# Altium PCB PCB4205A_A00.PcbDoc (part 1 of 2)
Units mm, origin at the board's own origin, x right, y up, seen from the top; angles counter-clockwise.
Board outline 30 x 60 mm, 4 copper layers (Top Layer, Signal Layer 2, Signal Layer 3, Bottom Layer), stack 1.526 mm thick; 55 components, 66 nets, 233 pads, 356 vias.
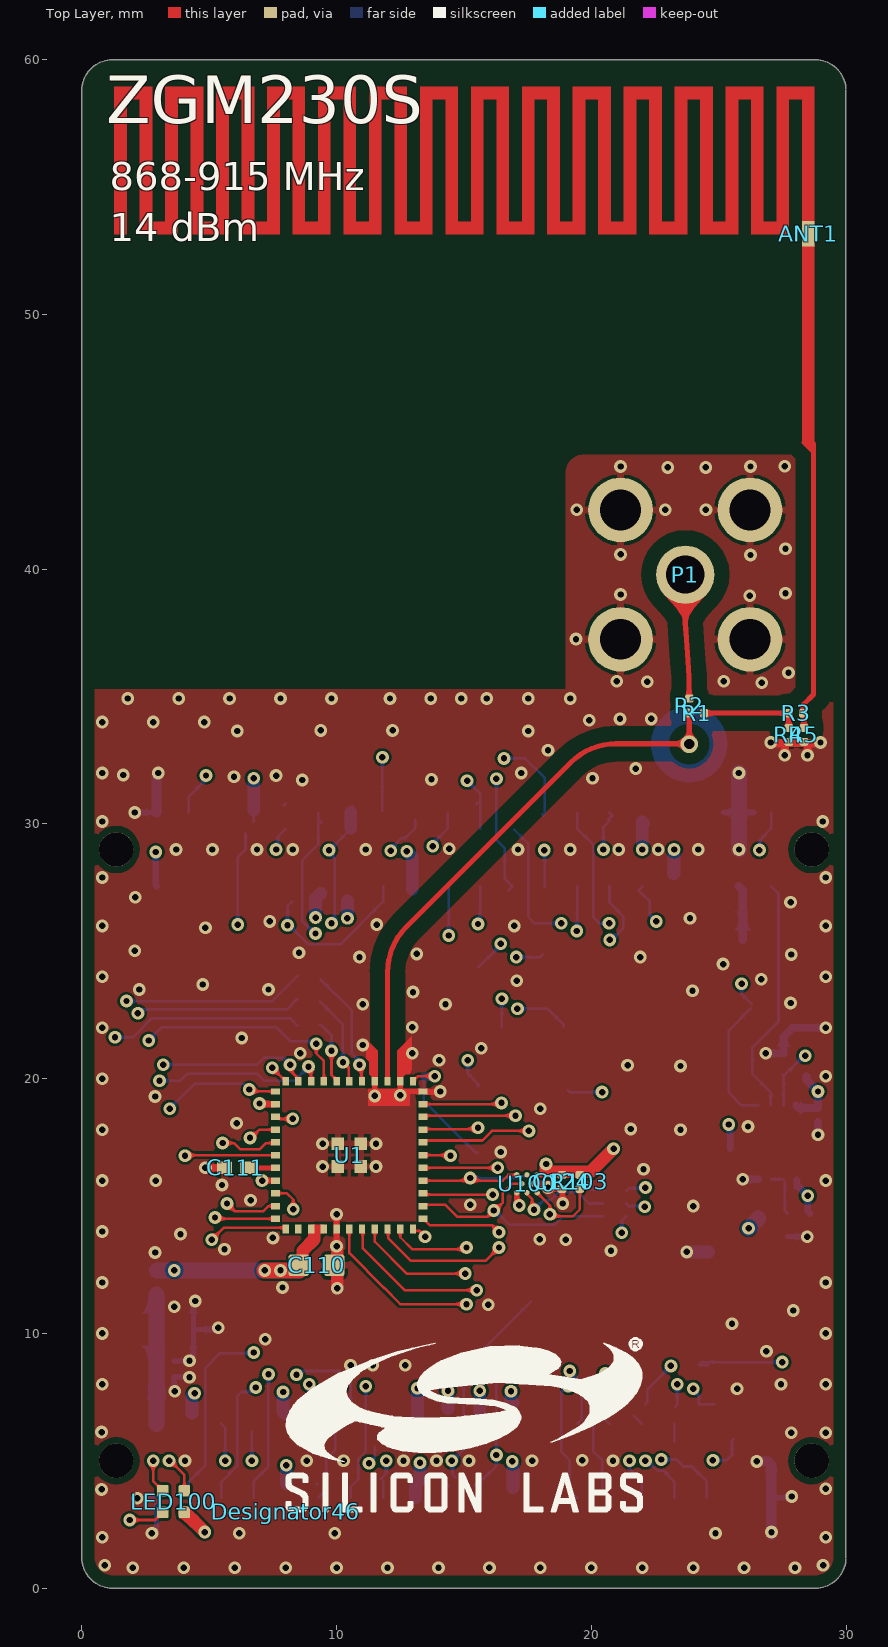
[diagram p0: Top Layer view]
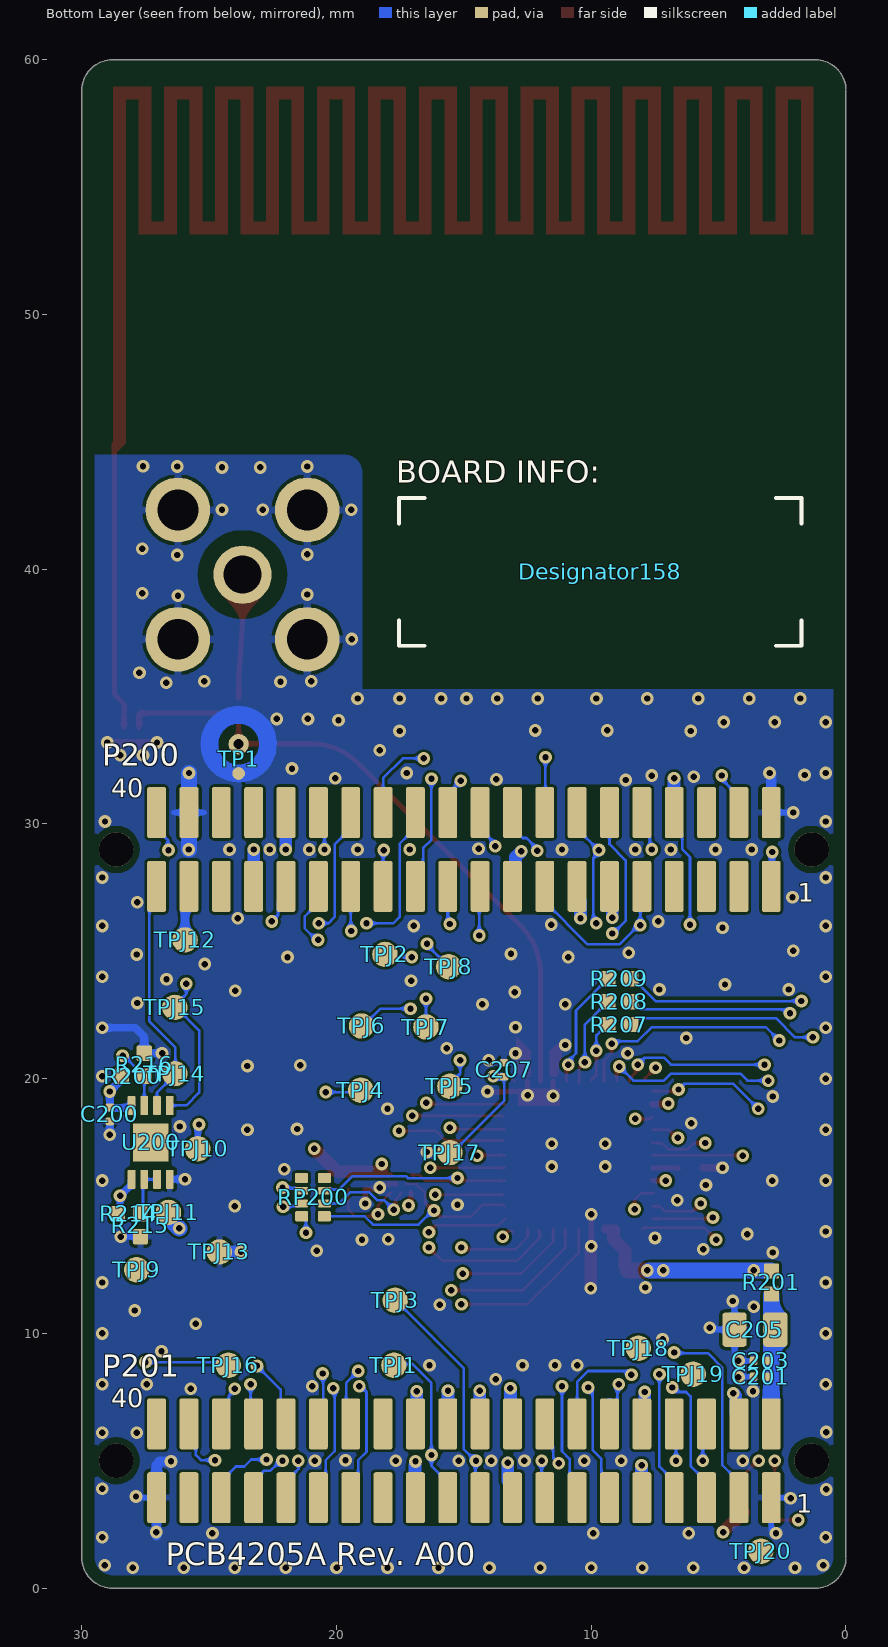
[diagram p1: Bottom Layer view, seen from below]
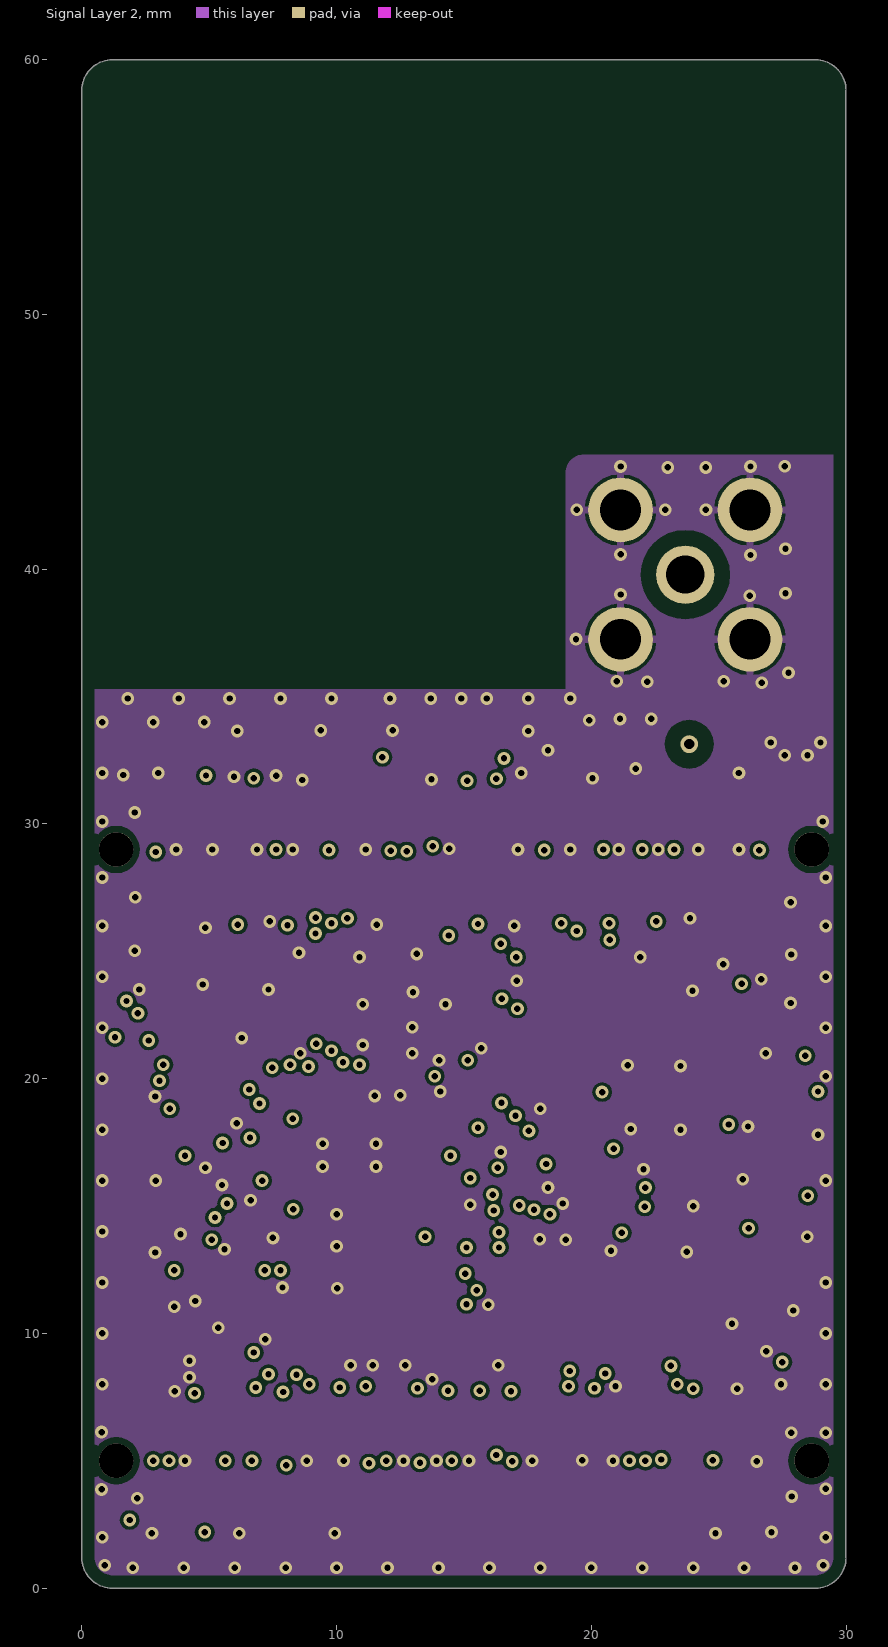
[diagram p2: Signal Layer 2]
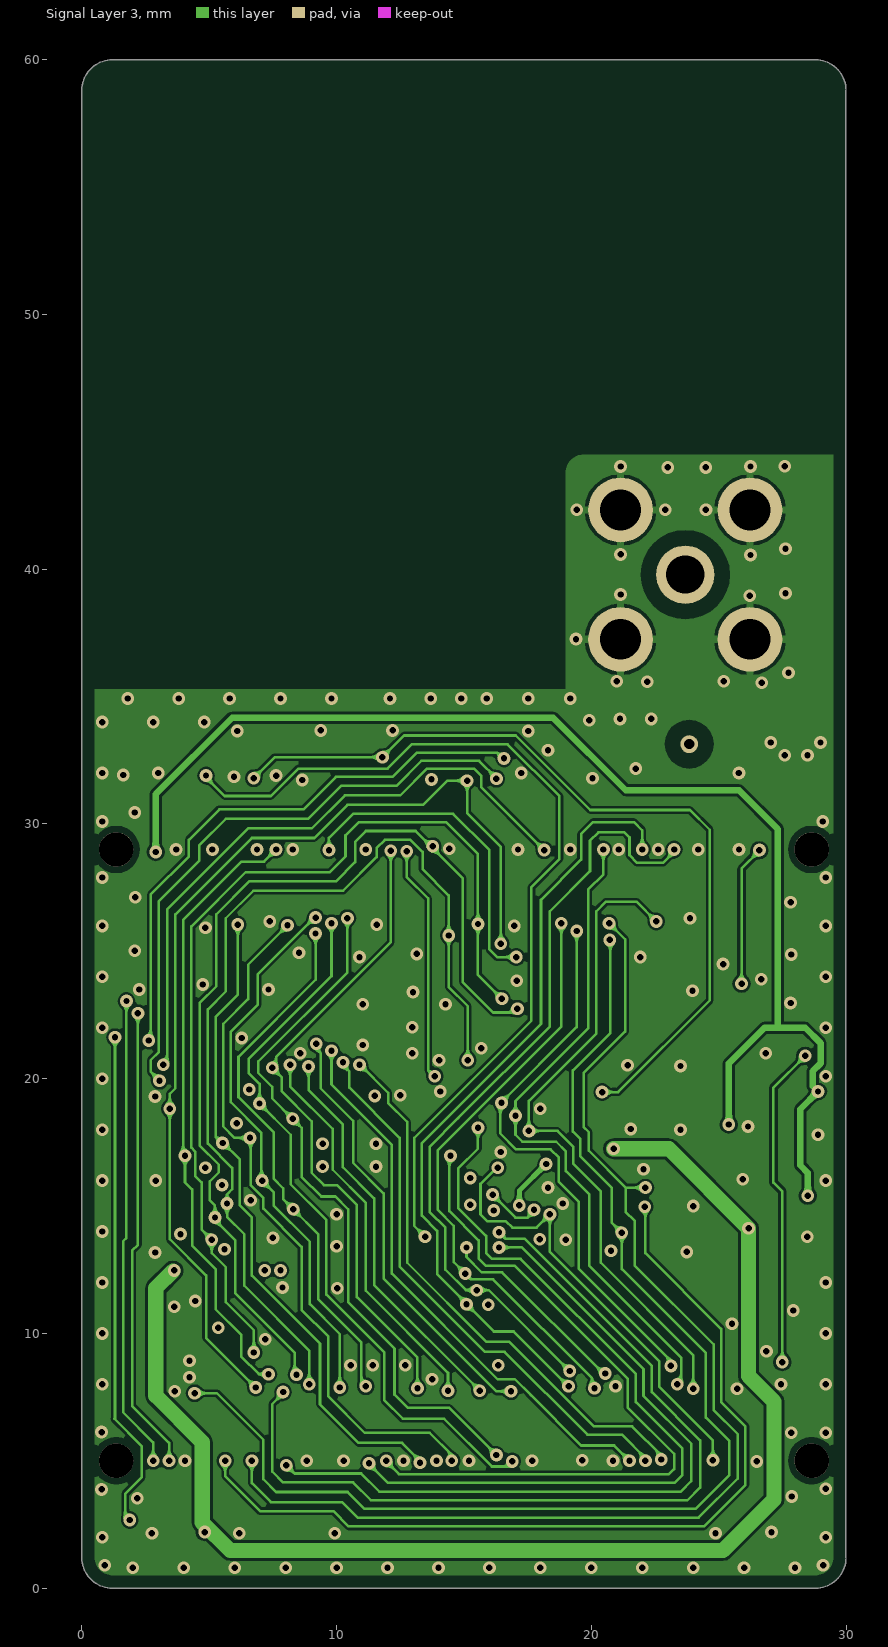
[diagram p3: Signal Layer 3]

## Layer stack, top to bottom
Top Solder: solder mask 0.01, Solder Resist, Dk 3.5
Top Layer: signal copper 0.035
Dielectric 1: core 0.132, 2116, Dk 4.2
Signal Layer 2: signal copper 0.018
Dielectric 3: prepreg 1.156, Dk 4.2
Signal Layer 3: signal copper 0.018
Dielectric 2: core 0.132, 2116, Dk 4.2
Bottom Layer: signal copper 0.035
Bottom Solder: solder mask 0.01, Solder Resist, Dk 3.5

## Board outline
0,1.2 ccw(c1.2,1.2) 1.2,0 28.8,0 ccw(c28.8,1.2) 30,1.2 30,58.8 ccw(c28.8,58.8) 28.8,60 1.2,60 ccw(c1.2,58.8) 0,58.8

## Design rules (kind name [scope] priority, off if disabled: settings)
AcuteAngle [All] p1: minimum=6.00000000000000E+0001 checktracksonly=FALSE
BoardOutlineClearance [All] p1: gap=0.5
Clearance Clearance_to_Holes [(InPadClass('NPTH')) and (HoleDiameter > AsMM(0.01))] p1: gap=0.254
Clearance Clearance_50Ohm [InNetClass('50Ohm') or InNet('50R_*') vs InPolygon] p2: gap=0.6
Clearance Clerance_Polygon_GND3 [InNamedPolygon('GND_3')] p3: gap=0.127
Clearance Clerance_Polygon_GND2 [InNamedPolygon('GND_2')] p4: gap=0.127
Clearance Clerance_Polygon_GND1 [InNamedPolygon('GND_L2')] p5: gap=0.127
Clearance Clerance_Polygon_GND4 [InNamedPolygon('GND_4')] p6: gap=0.127
Clearance Clearance_General [All] p7: gap=0.1
ComponentClearance Res_selector [InComponent('R1') or InComponent('R203')    or InComponent('R205') or InComponent('R214') or InComponent('R216') vs InComponent('R2') or InComponent('R204') or InComponent('R206')  or InComponent('R215') or InComponent('R200')] p1: gap=0 collisioncheckmode=3 verticalgap=0 showdistances=FALSE
ComponentClearance ComponentClearance_R1_R2 [InComponent('R1') vs InComponent('R2')] p2: gap=0 collisioncheckmode=3 verticalgap=0 showdistances=TRUE
ComponentClearance [All] p3: gap=0.2 collisioncheckmode=3 verticalgap=0.2 showdistances=TRUE
HoleToHoleClearance HoleToHoleClearance_ANT1toPAD [Incomponent ('ANT1') vs ISpad] p1: gap=0 allowstackedmicrovias=TRUE
HoleToHoleClearance HoleToHoleClearance_U1toVIA_1 [InComponent ('U1') vs IsVia] p2: gap=0 allowstackedmicrovias=TRUE
HoleToHoleClearance [All] p3: gap=0.254 allowstackedmicrovias=TRUE
MinimumSolderMaskSliver [All] p1: minsoldermaskwidth=0.102
NetAntennae [not InComponent('ANT1')] p1: netantennaetolerance=0
PolygonConnect PolygonConnect_SH100 [InComponent('SH100')] p1: connectstyle=Direct reliefconductorwidth=0.254 reliefentries=4 polygonreliefangle="90 Angle" airgapwidth=0.127
PolygonConnect PolygonConnect_P1 [InComponent('P1')] p2: connectstyle=Relief reliefconductorwidth=0.305 reliefentries=4 polygonreliefangle="90 Angle" airgapwidth=0.127
PolygonConnect Polygon_VIA_Connect [IsVia] p3: connectstyle=Direct reliefconductorwidth=0.254 reliefentries=4 polygonreliefangle="90 Angle" airgapwidth=0.254
PolygonConnect PolygonConnect_General [All] p4: connectstyle=Relief reliefconductorwidth=0.254 reliefentries=4 polygonreliefangle="90 Angle" airgapwidth=0.127
RoutingVias [All] p1: holewidth=0.25 width=0.5 viastyle="Through Hole" minholewidth=0.25 minwidth=0.5 maxholewidth=1 maxwidth=1.5
SilkToSilkClearance [All] p1: silktosilkclearance=0.102
SilkToSolderMaskClearance [IsPad] p1: minsilkscreentomaskgap=0.102 clearancetoexposedcopper=TRUE
SolderMaskExpansion [All] p1: expansion=0.051
ViasUnderSMD [(PadXSize_TopLayer > AsMM(1)) and (PadySize_TopLayer > AsMM(1))] p1: allowed=TRUE
Width [All] p1: maxlimit=5.08 minlimit=0.1 preferedwidth=0.127
24 further rules are at their usual default settings.

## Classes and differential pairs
net class 50Ohm: 50R_P1 50R_R1 50R_R4 N16865893
pad class NPTH: P200-M1 P200-M2 P201-M1 P201-M2

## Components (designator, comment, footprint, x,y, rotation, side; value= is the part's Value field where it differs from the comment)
ANT1 "Antenna" SWL_ANTENNA 1.27,53.15 r0 top
C110 "10U" C0603_L 9.213,12.672 r0 top
C111 "TBD" C0402_L 6.05,16.5 r180 top
C124 "100N" C0201_L 18.85,15.95 r270 top
C200 "100N" C0201_L 28.9,18.6 r270 bottom
C201 "100N" C0201_L 3.35,8.3 r0 bottom
C203 "100N" C0201_L 3.35,8.925 r0 bottom
C205 "10U" C0805_L 3.575,10.15 r0 bottom
C207 "100N" C0201_L 13.425,20.35 r90 bottom
Designator43 "Comment" PCB_SPEC_4_LAYER_ZWAVE -73.325,112.975 r0 top locked
Designator46 "Comment" LOGO_SILABS_W14.0 8,3 r0 top
Designator158 "Comment" PCB_Info_16x6 9.65,39.9 r180 bottom
LED100 "RGB" LED_LUMEX_SML_LX0404 3.6,3.4 r90 top
P1 "SMA" TE_SMA_TH_1814832 23.69,39.79 r0 top
P200 "SOCKET_WCON_2X20_1.27MM_SMD" SAM_SFC-120-T2-D-A-2X20_SNUM 15,29 r0 bottom locked
P201 "SOCKET_WCON_2X20_1.27MM_SMD" SAM_SFC-120-T2-D-A-2X20_SNUM 15,5 r0 bottom locked
R1 "0R" R0201_L 24.15,34.35 r0 top
R2 "0R" R0201_L 23.85,34.65 r90 top
R3 "0R" R0201_L 28.04,34.35 r0 top
R4 "0R" R0201_L 27.75,33.5 r270 top
R5 "0R" R0201_L 28.35,33.5 r270 top
R103 "330K" R0201_L 19.55,15.95 r90 top
R200 "10K" R0402_L 28,20.1 r0 bottom
R201 "0R" R0402_L 2.925,12 r90 bottom
R207 "8K2" R0402_L 8.9,22.125 r180 bottom
R208 "5K6" R0402_L 8.9,23.025 r180 bottom
R209 "4K7" R0402_L 8.9,23.925 r180 bottom
R214 "0R" R0402_L 28.15,14.7 r180 bottom
R215 "0R" R0402_L 27.7,14.25 r270 bottom
R216 "0R" R0402_L 27.55,20.55 r90 bottom
RP200 "100R" RES_MNR04-8 20.925,15.35 r90 bottom
TP1 "TP_RF" "TP_INGUN_50_OHM_CLOSED openvia" 23.845,33.135 r180 bottom
TPJ1 "TPJ_SMD" TP_1.0_SMD 17.75,8.75 r90 bottom locked
TPJ2 "TPJ_SMD" TP_1.0_SMD 18.1,24.88 r90 bottom locked
TPJ3 "TPJ_SMD" TP_1.0_SMD 17.7,11.3 r90 bottom locked
TPJ4 "TPJ_SMD" TP_1.0_SMD 19.05,19.55 r90 bottom locked
TPJ5 "TPJ_SMD" TP_1.0_SMD 15.55,19.7 r90 bottom locked
TPJ6 "TPJ_SMD" TP_1.0_SMD 19.02,22.07 r90 bottom locked
TPJ7 "TPJ_SMD" TP_1.0_SMD 16.49,22.03 r90 bottom locked
TPJ8 "TPJ_SMD" TP_1.0_SMD 15.6,24.4 r90 bottom locked
TPJ9 "TPJ_SMD" TP_1.0_SMD 27.85,12.5 r90 bottom locked
TPJ10 "TPJ_SMD" TP_1.0_SMD 25.45,17.25 r90 bottom locked
TPJ11 "TPJ_SMD" TP_1.0_SMD 26.6,14.75 r90 bottom locked
TPJ12 "TPJ_SMD" TP_1.0_SMD 25.95,25.45 r90 bottom locked
TPJ13 "TPJ_SMD" TP_1.0_SMD 24.6,13.2 r90 bottom locked
TPJ14 "TPJ_SMD" TP_1.0_SMD 26.35,20.2 r90 bottom locked
TPJ15 "TPJ_SMD" TP_1.0_SMD 26.35,22.8 r90 bottom locked
TPJ16 "TPJ_SMD" TP_1.0_SMD 24.25,8.75 r90 bottom locked
TPJ17 "TPJ_SMD" TP_1.0_SMD 15.55,17.1 r90 bottom locked
TPJ18 "TPJ_SMD" TP_1.0_SMD 8.15,9.42 r90 bottom locked
TPJ19 "TPJ_SMD" TP_1.0_SMD 6,8.4 r90 bottom locked
TPJ20 "TPJ_SMD" TP_1.0_SMD 3.34,1.45 r90 bottom locked
U1 "ZGM230SA27HNN0" ZGM230S 10.5,17 r270 top locked
U100 "MX25R8035F" BGA8_M040_1.24x1.75_WLCSP 17.475,15.875 r270 top
U200 "24AA024" TDFN8_M050_2.0X3.0_EP 27.3,17.5 r180 bottom

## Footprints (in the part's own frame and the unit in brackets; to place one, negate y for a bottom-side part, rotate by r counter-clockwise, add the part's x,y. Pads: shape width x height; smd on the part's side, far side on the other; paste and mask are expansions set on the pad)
BGA8_M040_1.24x1.75_WLCSP [mm] "BGA, 8 pin. U100"
  round 0.21 smd mask+0.051: A1(-0.35,0.4) A3(0.35,0.4) B2(0,0.2) C1(-0.35,0) C3(0.35,0) D2(0,-0.2) E1(-0.35,-0.4) E3(0.35,-0.4)
  body extent -0.63,-0.89 0.63,0.88, height 0.52
C0201_L [mm] "Capacitor, Chip; 0.60 mm L X 0.30 mm W X 0.33 mm H body"
  rrect52% 0.31x0.34 smd: 1(-0.275,0) 2(0.275,0)
  body extent -0.3,-0.15 0.3,0.15, height 0.3
C0402_L [mm] "Chip Capacitor, 2-Leads, Body 1.0x0.5mm, IPC High Density"
  rrect20% 0.6x0.5 smd mask+0.051: 1(-0.45,0) 2(0.45,0)
  body extent -0.5,-0.25 0.5,0.25, height 0.6
C0603_L [mm] "Capacitor, 0603, High Density (C)"
  rrect25% 0.8x0.85 smd: 1(-0.7,0) 2(0.7,0)
  body extent -0.88,-0.48 0.87,0.48, height 0.95
C0805_L [mm] "Capacitor, 0805"
  rrect25% 0.95x1.35 smd: 1(-0.8,0) 2(0.8,0)
  body extent -1.1,-0.72 1.1,0.72, height 1.45
LED_LUMEX_SML_LX0404 [mm] "LED, LUMEX, SML LX0404 1.0x1.0x0.25 NB! Pin numbering"
  rrect25% 0.45x0.45 smd mask+0.05: 1(-0.425,-0.425) 2(-0.425,0.425) 3(0.425,0.425) 4(0.425,-0.425)
  body extent -0.5,-0.5 0.5,0.5, height 0.31
LOGO_SILABS_W14.0 [mm] "LOGO_SILABS_W14.0"
  silkscreen extent 0.03,0 13.99,6.83
PCB_Info_16x6 [mm]
  silkscreen extent -7.9,-2.9 7.9,2.9
PCB_SPEC_4_LAYER_ZWAVE [mm]
R0201_L [mm] "Resistor, Chip; 0.60 mm L X 0.30 mm W X 0.28 mm H body"
  rrect52% 0.31x0.34 smd: 1(-0.275,0) 2(0.275,0)
  body extent -0.3,-0.15 0.3,0.15, height 0.23
R0402_L [mm] "Chip Resistor, 2-Leads, Body 1.0x0.5mm, IPC High Density"
  rrect20% 0.6x0.6 smd mask+0.051: 1(-0.45,0) 2(0.45,0)
  body extent -0.5,-0.25 0.5,0.25, height 0.6
RES_MNR04-8 [mm] "Chip resistor network 8pin"
  rrect20% 0.4x0.5 smd mask+0.051: 1(-0.75,-0.45) 4(0.75,-0.45) 5(0.75,0.45) 8(-0.75,0.45)
  rrect20% 0.3x0.5 smd mask+0.051: 2(-0.25,-0.45) 3(0.25,-0.45) 6(0.25,0.45) 7(-0.25,0.45)
  body extent -1,-0.4 1,0.4, height 0.5
SAM_SFC-120-T2-D-A-2X20_SNUM [mm]
  rrect20% 0.74x2 smd mask+0.05: 1(-12.065,1.45) 2(-12.065,-1.45) 3(-10.795,1.45) 4(-10.795,-1.45) 5(-9.525,1.45) 6(-9.525,-1.45) 7(-8.255,1.45) 8(-8.255,-1.45) 9(-6.985,1.45) 10(-6.985,-1.45) 11(-5.715,1.45) 12(-5.715,-1.45) 13(-4.445,1.45) 14(-4.445,-1.45) 15(-3.175,1.45) 16(-3.175,-1.45) 17(-1.905,1.45) 18(-1.905,-1.45) 19(-0.635,1.45) 20(-0.635,-1.45) 21(0.635,1.45) 22(0.635,-1.45) 23(1.905,1.45) 24(1.905,-1.45) 25(3.175,1.45) 26(3.175,-1.45) 27(4.445,1.45) 28(4.445,-1.45) 29(5.715,1.45) 30(5.715,-1.45) 31(6.985,1.45) 32(6.985,-1.45) 33(8.255,1.45) 34(8.255,-1.45) 35(9.525,1.45) 36(9.525,-1.45) 37(10.795,1.45) 38(10.795,-1.45) 39(12.065,1.45) 40(12.065,-1.45)
  round 1.35 hole 1.35 unplated paste-5.563 mask-5.563: M1(13.652,0) M2(-13.652,0)
  body extent -14.29,-2.1 14.29,2.16, height 4.67
SWL_ANTENNA [mm] "switchless antenna"
  rect 0.5x1 smd paste-1 mask-1: 1(27.25,0.02)
  Top Layer region: 0,5.3 1.5,5.3 1.5,5.8 0,5.8
  Top Layer region: 2,5.3 3.5,5.3 3.5,5.8 2,5.8
  Top Layer region: 4,5.3 5.5,5.3 5.5,5.8 4,5.8
  Top Layer region: 6,5.3 7.5,5.3 7.5,5.8 6,5.8
  Top Layer region: 8,5.3 9.5,5.3 9.5,5.8 8,5.8
  Top Layer region: 10,5.3 11.5,5.3 11.5,5.8 10,5.8
  Top Layer region: 12,5.3 13.5,5.3 13.5,5.8 12,5.8
  Top Layer region: 14,5.3 15.5,5.3 15.5,5.8 14,5.8
  Top Layer region: 16,5.3 17.5,5.3 17.5,5.8 16,5.8
  Top Layer region: 18,5.3 19.5,5.3 19.5,5.8 18,5.8
  Top Layer region: 20,5.3 21.5,5.3 21.5,5.8 20,5.8
  Top Layer region: 22,5.3 23.5,5.3 23.5,5.8 22,5.8
  Top Layer region: 24,5.3 25.5,5.3 25.5,5.8 24,5.8
  Top Layer region: 26,5.3 27.5,5.3 27.5,5.8 26,5.8
  Top Layer region: 25,0 26.5,0 26.5,0.5 25,0.5
  Top Layer region: 23,0 24.5,0 24.5,0.5 23,0.5
  Top Layer region: 21,0 22.5,0 22.5,0.5 21,0.5
  Top Layer region: 19,0 20.5,0 20.5,0.5 19,0.5
  Top Layer region: 17,0 18.5,0 18.5,0.5 17,0.5
  Top Layer region: 15,0 16.5,0 16.5,0.5 15,0.5
  Top Layer region: 13,0 14.5,0 14.5,0.5 13,0.5
  Top Layer region: 11,0 12.5,0 12.5,0.5 11,0.5
  Top Layer region: 9,0 10.5,0 10.5,0.5 9,0.5
  Top Layer region: 7,0 8.5,0 8.5,0.5 7,0.5
  Top Layer region: 5,0 6.5,0 6.5,0.5 5,0.5
  Top Layer region: 3,0 4.5,0 4.5,0.5 3,0.5
  Top Layer region: 1,0 2.5,0 2.5,0.5 1,0.5
  Top Layer region: 24,0 24.5,0 24.5,5.8 24,5.8
  Top Layer region: 25,0 25.5,0 25.5,5.8 25,5.8
  Top Layer region: 26,0 26.5,0 26.5,5.8 26,5.8
  Top Layer region: 27,-0.5 27.5,-0.5 27.5,5.8 27,5.8
  Top Layer region: 18,0 18.5,0 18.5,5.8 18,5.8
  Top Layer region: 19,0 19.5,0 19.5,5.8 19,5.8
  Top Layer region: 20,0 20.5,0 20.5,5.8 20,5.8
  Top Layer region: 21,0 21.5,0 21.5,5.8 21,5.8
  Top Layer region: 22,0 22.5,0 22.5,5.8 22,5.8
  Top Layer region: 23,0 23.5,0 23.5,5.8 23,5.8
  Top Layer region: 12,0 12.5,0 12.5,5.8 12,5.8
  Top Layer region: 13,0 13.5,0 13.5,5.8 13,5.8
  Top Layer region: 14,0 14.5,0 14.5,5.8 14,5.8
  Top Layer region: 15,0 15.5,0 15.5,5.8 15,5.8
  Top Layer region: 16,0 16.5,0 16.5,5.8 16,5.8
  Top Layer region: 17,0 17.5,0 17.5,5.8 17,5.8
  Top Layer region: 6,0 6.5,0 6.5,5.8 6,5.8
  Top Layer region: 7,0 7.5,0 7.5,5.8 7,5.8
  Top Layer region: 8,0 8.5,0 8.5,5.8 8,5.8
  Top Layer region: 9,0 9.5,0 9.5,5.8 9,5.8
  Top Layer region: 10,0 10.5,0 10.5,5.8 10,5.8
  Top Layer region: 11,0 11.5,0 11.5,5.8 11,5.8
  Top Layer region: 5,0 5.5,0 5.5,5.8 5,5.8
  Top Layer region: 4,0 4.5,0 4.5,5.8 4,5.8
  Top Layer region: 3,0 3.5,0 3.5,5.8 3,5.8
  Top Layer region: 2,0 2.5,0 2.5,5.8 2,5.8
  Top Layer region: 1,0 1.5,0 1.5,5.8 1,5.8
  Top Layer region: 0,0 0.5,0 0.5,5.8 0,5.8
TDFN8_M050_2.0X3.0_EP [mm] "TDFN8_M050_2.0x3.0_EP"
  rrect20% 0.3x0.75 smd mask+0.051: 1(-0.75,-1.45) 2(-0.25,-1.45) 3(0.25,-1.45) 4(0.75,-1.45) 5(0.75,1.45) 6(0.25,1.45) 7(-0.25,1.45) 8(-0.75,1.45)
  rect 1.4x1.5 smd mask+0.051: 9(0,0)
  body extent -1,-1.5 1,1.5, height 1
TE_SMA_TH_1814832 [mm]
  round 2.286 hole 1.5: 1(0,0)
  round 2.54 hole 1.6: 2(-2.54,-2.54) 3(2.54,-2.54) 4(2.54,2.54) 5(-2.54,2.54)
  body extent -3.2,-3.2 3.2,3.2, height 9.5
TP_1.0_SMD [mm] "Test Point, 1.0 mm, SMD"
  round 1 smd paste-0.501: 1(0,0)
  body extent -0.5,-0.5 0.5,0.5, height 0.01
"TP_INGUN_50_OHM_CLOSED openvia" [mm] "TP_INGUN_50_OHM_CLOSED"
  round 0.8 / inner round 0.7 / far side round 0.7 hole 0.4 mask+0: 1(0,0)
  round 0.5 smd paste-0.255 mask-0.41: 2(0,-1.15)
  Top Layer pour cut-out: 0,-0.8 0.4,-0.693 0.693,-0.4 0.8,0 0.693,0.4 0.4,0.693 0,0.8 0,0.8 -0.347,0.721 -0.625,0.499 -0.78,0.178 -0.78,-0.178 -0.625,-0.499 -0.347,-0.721 0,-0.8
  Top Layer lines w0.7: 0,-1.15 ccw(c0,0) -1.15,0 ccw(c0,0) 0,-1.15
ZGM230S [mm] "no datasheet"
  rect 0.35x0.25 smd paste-0.03 mask+0.04: 1(-2.9,2.5) 2(-2.9,2) 3(-2.9,1.5) 4(-2.9,1) 5(-2.9,0.5) 6(-2.9,0) 7(-2.9,-0.5) 8(-2.9,-1) 9(-2.9,-1.5) 10(-2.9,-2) 11(-2.9,-2.5) 23(2.9,-2.5) 24(2.9,-2) 25(2.9,-1.5) 26(2.9,-1) 27(2.9,-0.5) 28(2.9,0) 29(2.9,0.5) 30(2.9,1) 31(2.9,1.5) 32(2.9,2) 33(2.9,2.5)
  rect 0.25x0.35 smd paste-0.03 mask+0.04: 12(-2.5,-2.9) 13(-2,-2.9) 14(-1.5,-2.9) 15(-1,-2.9) 16(-0.5,-2.9) 17(0,-2.9) 18(0.5,-2.9) 19(1,-2.9) 20(1.5,-2.9) 21(2,-2.9) 22(2.5,-2.9) 34(2.5,2.9) 35(2,2.9) 36(1.5,2.9) 37(1,2.9) 38(0.5,2.9) 39(0,2.9) 40(-0.5,2.9) 41(-1,2.9) 42(-1.5,2.9) 43(-2,2.9) 44(-2.5,2.9)
  rect 0.5x0.5 smd paste-0.03 mask+0.04: 45(-0.45,0.45) 46(-0.45,-0.45) 47(0.45,-0.45) 48(0.45,0.45)
  body extent -3.25,-3.25 3.25,3.25, height 1.3

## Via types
v1: diameter 0.5, hole 0.25, Top Layer to Bottom Layer, tented both sides, 356 vias

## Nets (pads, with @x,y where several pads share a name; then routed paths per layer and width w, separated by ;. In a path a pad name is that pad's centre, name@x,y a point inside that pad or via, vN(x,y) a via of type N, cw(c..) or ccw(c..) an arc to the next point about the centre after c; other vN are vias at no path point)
3V3: C200.1 P200.1 R200.2 R214.1 TPJ10.1 U200.1 U200.8 | length 57.3
  Signal Layer 3 w0.254: v1(2.9,28.9) 2.9,31.175 5.9,34.175 18.5,34.175 21.35,31.325 25.8,31.325 27.325,29.8 27.325,22.05 ; v1(25.4,18.2) 25.4,20.6 26.8,22 28.4,22 29,21.4 29,20.6 28.7,20.3 28.7,19.7 v1(28.9,19.5) 28.2,18.8 28.2,16.6 28.5,16.3 v1(28.5,15.4)
  Bottom Layer w0.254: v1(2.9,28.9) 2.9,27.585 P200.1@2.935,27.55 ; v1(25.4,18.2) 25.45,18.25 TPJ10.1@25.45,17.25 ; U200.1@28.075,16.025 28.075,15.825 v1(28.5,15.4) 28.5,14.8 R214.1@28.6,14.7
  Bottom Layer w0.305: U200.8@28.05,18.95 28.15,18.85 28.9,18.85 C200.1@28.9,18.875 v1(28.9,19.5) 28.45,19.95 R200.2@28.45,20.1
5V: P200.37 TPJ12.1 | length 2.2
  Bottom Layer w0.33: P200.37@25.795,27.55 25.95,27.395 TPJ12.1@25.95,25.45
50R_P1: P1.1 R2.2 | length 4.8
  Top Layer w0.2: P1.1@23.69,39.79 23.69,37.9 23.734,37.25 23.791,36.399 23.84,35.775 23.84,34.96 R2.2@23.85,34.95
50R_R1: R1.1 R2.1 TP1.1 U1.3 | length 21.4
  Top Layer w0.2: U1.3@12,19.9 12,24.173 cw(c14.54,24.173) 12.744,25.969 19.181,32.406 cw(c20.977,30.61) 20.977,33.15 TP1.1@23.845,33.15 ; R1.1@23.84,34.35 23.845,34.345 TP1.1@23.845,33.15 ; TP1.1@23.85,33.15 TP1.1@23.845,33.15
50R_R4: R1.2 R3.1 R4.1 | length 3.8
  Top Layer w0.2: R1.2@24.45,34.35 27.74,34.35 27.75,34.34 R4.1@27.75,33.8
BOARD_ID_SCL: P200.39 TPJ14.1 U200.6 | length 9.3
  Bottom Layer w0.1: TPJ14.1@26.325,20.175 27.05,19.45 U200.6@27.05,18.95 ; TPJ14.1@26.325,20.275 26.325,21.225 27.35,22.25 27.35,27.265 P200.39@27.065,27.55
BOARD_ID_SDA: P200.40 TPJ15.1 U200.5 | length 13.1
  Signal Layer 3 w0.1: v1@25.9,23.75 25.9,28.25 26.6,28.95 v1(26.6,28.975)
  Bottom Layer w0.1: v1(25.9,23.725) 25.9,23.325 TPJ15.1@26.3,22.925 ; TPJ15.1@26.275,22.775 25.4,21.9 25.4,19.45 25.9,18.95 U200.5@26.55,18.95 ; v1@26.675,29.05 26.625,29.1 26.625,29.375 27.065,29.815 P200.40@27.065,30.45
BOARD_ID_WP: R200.1 R216.1 TPJ16.1 U200.7 | length 18.7
  Signal Layer 3 w0.1: v1(27.5,8.875) 27.5,15.575 27.15,15.925 27.15,19.65 v1(28.4,20.9)
  Bottom Layer w0.1: TPJ16.1@24.225,8.775 24.325,8.875 v1(27.5,8.875) ; TPJ16.1@24.25,8.75 TPJ16.1@24.595,8.75 ; R200.1@27.525,20.15 27.55,20.125 U200.7@27.55,18.95 ; R200.1@27.55,20.1 28.3,20.85 v1@28.375,20.85
FLASH_MISO: RP200.2 U1.36 U100.C3 | length 8.4
  Top Layer w0.1: U1.36@13.475,15.45 15.85,15.45 ; U100.C3@17.475,15.525 17.475,15.475 17.675,15.275 17.675,14.975 v1@17.725,14.925
  Signal Layer 3 w0.1: v1(16.125,15.45) 17.025,14.55 17.5,14.55 17.65,14.7 v1@17.65,14.9
  Bottom Layer w0.1: v1(17.751,14.851) 18.125,15.225 18.4,15.225 18.725,15.55 19.45,15.55 19.9,15.1 RP200.2@20.45,15.1
FLASH_MOSI: RP200.1 U1.35 U100.D2 | length 9.4
  Top Layer w0.1: U1.35@13.425,15 13.475,15.05 14.275,15.05 14.75,14.575 15.925,14.575 v1(16.175,14.825) ; v1@16.25,14.85 16.525,15.125 16.525,15.525 16.875,15.875 U100.D2@17.275,15.875
  Bottom Layer w0.1: v1(16.175,14.825) 16.2,14.85 16.775,14.275 18.575,14.275 18.9,14.6 RP200.1@20.475,14.6
FLASH_SCLK: RP200.3 U1.37 U100.E1 | length 9.3
  Top Layer w0.1: U1.37@13.4,16 16.525,16 16.75,16.225 U100.E1@17.075,16.225
  Bottom Layer w0.1: v1(15.25,16.1) 17.2,16.1 17.275,16.175 19.375,16.175 19.9,15.65 20.475,15.65 RP200.3@20.5,15.625
FLASH_SCS: P201.38 R103.1 U1.38 U100.A3 | length 25.2
  Top Layer w0.1: U1.38@13.4,16.5 16.125,16.5 16.25,16.625 16.325,16.55 v1(16.325,16.5) ; U100.A3@17.875,15.525 18.375,15.025 v1@18.375,14.7 ; v1@18.375,14.6 19.275,14.6 19.55,14.875 R103.1@19.55,15.675
  Signal Layer 3 w0.1: v1(16.325,16.5) 16.275,16.5 15.65,15.875 15.65,14.675 15.925,14.4 16.65,14.4 16.9,14.15 17.85,14.15 v1(18.375,14.675) 18.375,13.2 22.675,8.9 22.675,7.9 24.775,5.8 v1@24.775,5.05
  Bottom Layer w0.1: v1(24.775,5.025) 25.325,5.025 25.525,5.225 25.525,5.775 P201.38@25.6,5.85
GND: C110.2 C111.2 C124.2 C200.2 C201.2 C203.2 C205.2 C207.2 P1.2 P1.3 P1.4 P1.5 P200.2 P200.38 P201.1 P201.39 R4.2 R5.2 R215.2 R216.2 TP1.2 TPJ13.1 U1.2 U1.4 U1.27 U1.44 U1.45 U1.46 U1.47 U1.48 U100.B2 U200.4 | length 35.1
  Top Layer w0.2: v1@9.975,14.675 10,14.65 U1.27@10,14.1 v1(10,13.425) ; v1@11.5,19.3 U1.4@11.5,19.9 ; v1@12.45,19.375 12.5,19.425 U1.2@12.5,19.9 ; v1@12.55,19.45 12.6,19.5 U1.44@13.4,19.5 13.425,19.475 v1@13.95,19.475 ; U100.B2@17.675,15.875 18.1,15.875 ; v1@18.325,15.75 18.4,15.675 C124.2@18.85,15.675 18.875,15.65 v1(18.875,15.1)
  Top Layer w0.3: v1(4.85,16.5) C111.2@5.6,16.5
  Top Layer w0.305: v1(27.05,33.2) 27.14,33.2 27.165,33.175 R5.2@28.49,33.175 ; v1@27.59,32.7 R4.2@27.59,33.125 ; v1(28.49,32.7) 28.49,33.175 28.975,33.175 v1(29,33.2)
  Top Layer w0.5: v1(10,13.425) 10.025,13.4 v1(10.025,11.775)
  Bottom Layer w0.2: v1@2.2,30.45 P200.2@2.935,30.45 ; v1@2.32,3.55 P201.1@2.935,3.55 2.935,2.31 v1@2.775,2.15 ; v1@3.625,7.7 C201.2@3.625,8.3 4.225,8.3 v1@4.25,8.275 ; C203.2@3.625,8.925 v1(4.225,8.925) ; v1@4.25,8.85 4.375,8.975 C205.2@4.375,10.15 ; v1(4.45,11.275) 4.375,11.2 C205.2@4.375,10.15 ; v1@5.375,10.225 5.3,10.15 C205.2@4.375,10.15 ; v1@14.05,19.525 v1(14.075,19.5) ; 25.18,30.45 P200.38@25.795,30.45 25.8,30.45 26.41,30.45 ; P201.39@27.065,3.55 v1@27.68,3.55 ; R215.2@27.7,13.8 v1(28.475,13.8) v1@28.5,13.825
  Bottom Layer w0.305: 24.995,33.135 25.16,33.3 ; v1(25.95,16.05) U200.4@26.55,16.05 ; v1@26.825,20.975 v1(26.85,21) R216.2@27.55,21 27.55,21.65 27.9,22 v1(29.2,22) ; v1(28.9,17.8) C200.2@28.9,18.3
  Bottom Layer w0.4: P200.2@2.935,30.45 2.935,31.935 v1(3,32) ; v1@26.45,5.025 v1(26.5,4.975) 26.925,4.975 27.065,4.835 P201.39@27.065,3.55 v1@27.065,2.065
  Bottom Layer w0.5: v1(23.75,13.2) TPJ13.1@24.6,13.2
  Bottom Layer w0.635: P200.38@25.775,30.55 P200.38@25.795,30.53 ; v1(25.795,32) P200.38@25.795,30.53 ; v1(25.8,29) P200.38@25.8,30.445 ; P200.38@25.795,30.53 25.8,30.525 25.8,30.45 P200.38@25.8,30.445 ; P200.38@25.795,30.53 P200.38@25.795,30.45 P200.38@25.8,30.445
  other v1: 2,0.8 4,0.8 6,0.8 8,0.8 10,0.8 12,0.8 14,0.8 16,0.8 18,0.8 20,0.8 22,0.8 24,0.8 26,0.8 28,0.8 0.9,0.9 29.1,0.9 0.8,2 29.2,2 2.75,2.15 6.175,2.15 9.925,2.15 24.875,2.15 27.075,2.2 2.175,3.525 27.875,3.6 0.775,3.875 29.2,3.9 4.05,5 8.825,5 10.275,5 12.625,5 13.925,5 15.2,5 17.675,5 20.85,5 19.65,5.025 27.85,6.1 29.2,6.1 0.775,6.125 3.65,7.725 25.725,7.825 20.95,7.925 0.8,8 27.45,8 29.2,8 13.75,8.2 4.225,8.275 10.55,8.75 11.425,8.75 12.7,8.75 16.35,8.75 26.875,9.3 7.2,9.775 0.8,10 29.2,10 5.35,10.225 25.525,10.375 27.925,10.9 3.625,11.05 15.95,11.125 7.875,11.801 0.8,12 29.2,12 2.875,13.175 20.775,13.25 5.6,13.3 19,13.675 17.975,13.7 7.5,13.75 3.875,13.9 0.8,14 10,14.675 24,15 15.25,15.05 6.625,15.225 18.3,15.725 5.5,15.825 0.8,16 2.9,16 29.2,16 22.05,16.45 9.45,16.55 11.55,16.55 16.45,17.125 9.45,17.45 11.55,17.45 0.8,18 23.5,18 21.55,18.025 26.15,18.125 6.075,18.25 18,18.825 2.875,19.3 11.5,19.325 12.5,19.35 0.8,20 29.2,20.1 23.5,20.5 21.425,20.525 14.025,20.725 8.575,21 12.975,21 15.675,21.2 11.025,21.325 6.275,21.6 0.8,22 12.975,22.025 11.025,22.925 14.275,22.925 27.825,22.975 13,23.4 23.975,23.45 2.25,23.5 7.325,23.5 4.75,23.7 17.075,23.85 26.675,23.9 0.8,24 29.2,24 25.175,24.5 10.9,24.775 21.925,24.775 27.85,24.875 13.15,24.9 8.525,24.95 2.075,25.025 4.85,25.925 0.8,26 16.975,26 29.2,26 11.575,26.05 7.375,26.175 23.875,26.3 27.825,26.925 2.1,27.125 0.8,27.9 29.2,27.9 3.7,29.001 5.125,29.001 6.875,29 8.275,29 11.15,29 17.125,29 19.175,29 21.075,29 22.625,29 24.2,29 14.425,29.025 0.8,30.1 29.09,30.1 2.075,30.45 8.65,31.725 13.725,31.75 20.05,31.8 5.975,31.852 7.625,31.9 1.625,31.925 0.8,32 17.25,32 21.75,32.175 27.6,32.7 18.3,32.9 6.1,33.65 17.525,33.65 9.375,33.675 12.2,33.675 0.8,34 2.8,34 4.8,34 19.925,34.075 21.125,34.125 22.35,34.125 1.8,34.925 3.8,34.925 5.8,34.925 7.8,34.925 9.8,34.925 12.1,34.925 13.697,34.925 14.897,34.925 15.897,34.925 17.525,34.925 19.175,34.925 26.69,35.55 22.2,35.585 20.997,35.6 25.2,35.6 27.74,35.94 19.4,37.26 26.225,38.96 21.15,39.01 27.625,39.06 26.25,40.56 21.15,40.585 27.625,40.81 19.425,42.335 22.9,42.335 24.5,42.335 22.997,44 24.497,44 21.15,44.035 26.25,44.035 27.6,44.05
LED_B: P201.35 R209.1 U1.5 | length 29.8
  Top Layer w0.1: v1(10.9,20.55) 10.8,20.55 10.975,20.725 10.975,19.925 U1.5@10.95,19.9
  Signal Layer 3 w0.1: v1(10.9,20.55) 10.925,20.55 12.025,19.45 12.025,19.05 12.775,18.3 12.775,12.775 15.875,9.675 16.775,9.675 18.55,7.9 20.1,6.35 21.6,6.35 22.75,5.2 v1(22.75,5.05)
  Bottom Layer w0.1: R209.1@9.375,23.9 10.6,22.675 10.6,21 10.937,20.663 10.9,20.625 v1(10.9,20.55) ; v1(22.75,5.05) 23.35,5.05 23.625,4.775 23.95,4.775 24,4.725 24.525,4.2 P201.35@24.525,3.55
LED_G: P201.33 R208.1 U1.6 | length 27.6
  Top Layer w0.1: v1(10.251,20.651) 10.251,20.65 10.475,20.425 10.475,19.925 U1.6@10.5,19.9 ; U1.6@10.475,19.825 U1.6@10.5,19.85
  Signal Layer 3 w0.1: v1(10.251,20.651) 10.251,20.525 10.5,20.275 10.5,19.65 12.475,17.675 12.475,12.625 15.825,9.275 16.6,9.275 19.85,6.025 21.2,6.025 22.125,5.1 v1(22.125,5)
  Bottom Layer w0.1: R208.1@9.35,23.025 10.251,22.124 v1(10.251,20.651) ; v1(22.125,5) 22.225,5 22.325,4.9 22.325,4.884 22.609,4.6 22.85,4.6 23.255,4.195 P201.33@23.255,3.55
LED_R: P201.31 R207.1 U1.7 | length 26.2
  Top Layer w0.1: v1(9.8,21.101) 9.8,20.15 U1.7@10,19.95
  Signal Layer 3 w0.1: 9.8,20.275 9.8,19.775 12.175,17.4 12.175,12.35 16.325,8.2 17,8.2 17.625,7.575 19.6,5.6 20.9,5.6 v1(21.5,5) ; 9.8,20.275 v1(9.8,21.101)
  Bottom Layer w0.1: R207.1@9.35,22.125 9.375,22.125 9.8,21.7 ; v1(9.8,21.101) 9.8,21.7 ; v1(21.5,5) 21.5,4.675 21.985,4.19 P201.31@21.985,3.55
MODULE_#RESET: C207.1 P200.17 TPJ17.1 U1.1 | length 16.1
  Top Layer w0.1: U1.1@13,19.9 13.201,20.101 v1(13.851,20.101)
  Signal Layer 3 w0.1: v1(12.75,28.925) 12.75,27.925 13.6,27.075 13.6,20.325 13.824,20.101 v1(13.851,20.101)
  Bottom Layer w0.1: C207.1@13.425,20.05 13.425,19.127 14.676,17.876 15.452,17.1 TPJ17.1@15.55,17.1 ; v1@13.825,20.075 v1(13.851,20.101)
  Bottom Layer w0.3: C207.1@13.425,20.075 v1@13.825,20.075
  Bottom Layer w0.5: v1(12.75,28.925) 12.975,28.7 P200.17@12.975,27.45
MODULE_PA10: P200.21 P201.3 TPJ7.1 U1.23 | length 51
  Top Layer w0.1: v1(5.1,13.675) 5.575,14.15 7.95,14.15 U1.23@8,14.1
  Signal Layer 3 w0.1: v1(6.75,9.25) 6.75,10.125 5.65,11.225 5.65,12.6 5.1,13.15 v1(5.1,13.675) 4.7,14.075 4.7,15.925 4.45,16.175 4.45,17.141 4.3,17.291 4.3,25.975 6.435,28.11 9.735,28.11 10.35,28.725 10.35,29.55 10.875,30.075 14.3,30.075 15.55,28.825 v1(15.55,26.075) 15.55,24.075 v1(16.49,23.135)
  Bottom Layer w0.1: P201.3@4.205,3.55 4.205,4.18 4.85,4.825 4.85,8.65 5.425,9.225 6.725,9.225 v1(6.75,9.25) ; v1(15.55,26.075) 15.635,26.16 P200.21@15.635,27.55 ; TPJ7.1@16.49,22.03 v1(16.49,23.135)
MODULE_PB00: P200.18 P201.18 U1.11 | length 29.6
  Top Layer w0.1: v1@7.475,20.425 U1.11@8,19.9
  Signal Layer 3 w0.1: v1(12.126,28.951) 12.126,25.351 7.625,20.85 7.625,20.576 v1(7.475,20.426) 7.85,20.051 7.85,19.5 9.025,18.325 9.025,16.3 9.5,15.825 10.025,15.825 10.8,15.05 10.8,11.425 13.175,9.05 v1(13.175,7.85)
  Bottom Layer w0.1: v1@12.05,28.95 12.55,29.45 12.7,29.45 13.095,29.845 P200.18@13.095,30.175 ; P201.18@13.05,6.5 P201.18@13.175,6.625 ; v1@13.125,7.8 v1@13.125,7.85
  Bottom Layer w0.5: P201.18@13.175,6.625 v1(13.175,7.85)
MODULE_PB01: P200.25 P201.20 U1.10 | length 48.4
  Top Layer w0.1: v1(8.175,20.55) 8.175,20.325 8.5,20 U1.10@8.5,19.9
  Signal Layer 3 w0.1: v1(3.2,20.55) 3.35,20.7 3.35,26.65 6.525,29.825 9.025,29.825 10.325,31.125 12.5,31.125 13.55,32.175 15.4,32.175 15.687,31.888 15.687,31.438 v1(18.15,28.975) ; v1(8.175,20.55) 8.175,19.7 9.85,18.025 9.85,16.425 11.15,15.125 11.15,11.675 14.375,8.45 v1(14.375,7.75)
  Bottom Layer w0.1: v1(3.2,20.55) 6.875,20.55 7.151,20.826 7.75,20.826 ; 7.75,20.825 7.9,20.825 v1(8.175,20.55) ; P201.20@14.3,6.975 P201.20@14.375,7.05 ; v1(18.15,28.975) 18.175,28.95 P200.25@18.175,27.55
  Bottom Layer w0.5: P201.20@14.375,7.05 v1(14.375,7.75)
MODULE_PB02: P200.23 P201.22 U1.9 | length 51.9
  Top Layer w0.1: v1@8.95,20.45 9,20.4 U1.9@9,19.9
  Signal Layer 3 w0.1: v1@3.05,19.991 v1(3.05,19.925) 2.7,20.275 2.7,20.725 3.025,21.05 3.025,26.975 4.6,28.55 4.6,29.15 5.65,30.2 8.875,30.2 10.175,31.5 12.35,31.5 13.325,32.475 15.6,32.475 16.275,31.8 v1(16.275,31.775) ; v1@8.9,20.45 8.9,19.55 10.25,18.2 10.25,16.525 11.475,15.3 11.475,11.9 v1(15.625,7.75)
  Bottom Layer w0.1: v1@3.075,20.026 2.974,20.026 3.05,19.95 v1(3.05,19.925) 3.875,19.925 4.15,20.2 6.875,20.2 7.15,19.925 8.35,19.925 v1(8.9,20.475) ; P201.22@15.55,6.75 P201.22@15.625,6.825 ; v1(16.275,31.775) v1(16.275,31.775) ; v1(16.275,31.775) 16.276,29.374 16.6,29.05 16.6,27.855 P200.23@16.905,27.55 P200.23@16.75,27.395
  Bottom Layer w0.5: P201.22@15.625,6.825 v1(15.625,7.75)
MODULE_PB03: P200.26 P201.24 U1.8 | length 52.1
  Top Layer w0.1: v1(9.2,21.376) 9.2,21 9.5,20.7 U1.8@9.5,19.9
  Signal Layer 3 w0.1: v1@2.7,21.65 2.7,27.225 4.2,28.725 4.2,29.375 5.4,30.575 8.7,30.575 9.975,31.85 12.2,31.85 13.15,32.8 16.3,32.8 16.525,32.575 v1(16.575,32.575) ; v1@9.1,21.275 9.375,21 9.375,19.625 10.65,18.35 10.65,16.7 11.85,15.5 11.85,12.15 16.275,7.725 v1(16.85,7.725)
  Bottom Layer w0.1: v1(2.625,21.5) 3.15,22.025 7.625,22.025 8.175,21.475 9.125,21.475 v1@9.275,21.325 ; v1(16.575,32.575) 17.4,32.575 18.175,31.8 P200.26@18.175,30.45 ; P200.26@18.075,30.375 P200.26@18.125,30.325
  Bottom Layer w0.5: P201.24@16.8,7.15 16.925,7.275 16.85,7.35 v1(16.85,7.725)
MODULE_PC00: P201.10 U1.34 | length 38.6
  Top Layer w0.1: U1.34@13.4,14.5 13.65,14.25 16.101,14.25 v1(16.376,13.976)
  Signal Layer 3 w0.1: v1(7.9,7.7) 7.9,7.65 7.475,7.225 7.475,4.575 7.9,4.15 10.65,4.15 11.35,3.45 23.775,3.45 24.275,3.95 24.275,5.8 22.375,7.7 22.375,8.725 17.375,13.725 16.626,13.725 v1(16.376,13.976)
  Bottom Layer w0.5: v1(7.9,7.7) 7.9,6.925 P201.10@8,6.825
MODULE_PC05: P201.15 U1.39 | length 30.8
  Top Layer w0.1: U1.39@13.4,17 14.475,17 14.5,16.975 v1(14.475,16.975)
  Signal Layer 3 w0.1: v1(11.95,5) 11.95,4.975 12.45,4.475 23.05,4.475 23.25,4.675 23.25,5.275 21.425,7.1 21.425,8.225 17,12.65 15.875,12.65 15.575,12.95 15.575,13.65 14.425,14.8 14.425,16.925 v1(14.475,16.975)
  Bottom Layer w0.1: P201.15@11.738,4.287 11.95,4.5 v1(11.95,5) ; P201.15@11.825,3.55 P201.15@11.825,4.2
